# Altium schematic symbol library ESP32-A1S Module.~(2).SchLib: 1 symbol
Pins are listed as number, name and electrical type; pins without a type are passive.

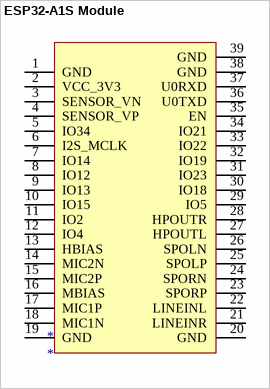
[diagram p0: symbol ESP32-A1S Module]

## ESP32-A1S Module
designator *
pins: 1 GND, 2 VCC_3V3, 3 SENSOR_VN, 4 SENSOR_VP, 5 IO34, 6 I2S_MCLK, 7 IO14, 8 IO12, 9 IO13, 10 IO15, 11 IO2, 12 IO4, 13 HBIAS, 14 MIC2N, 15 MIC2P, 16 MBIAS, 17 MIC1P, 18 MIC1N, 19 GND, 20 GND, 21 LINEINR, 22 LINEINL, 23 SPORP, 24 SPORN, 25 SPOLP, 26 SPOLN, 27 HPOUTL, 28 HPOUTR, 29 IO5, 30 IO18, 31 IO23, 32 IO19, 33 IO22, 34 IO21, 35 EN, 36 U0TXD, 37 U0RXD, 38 GND, 39 GND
